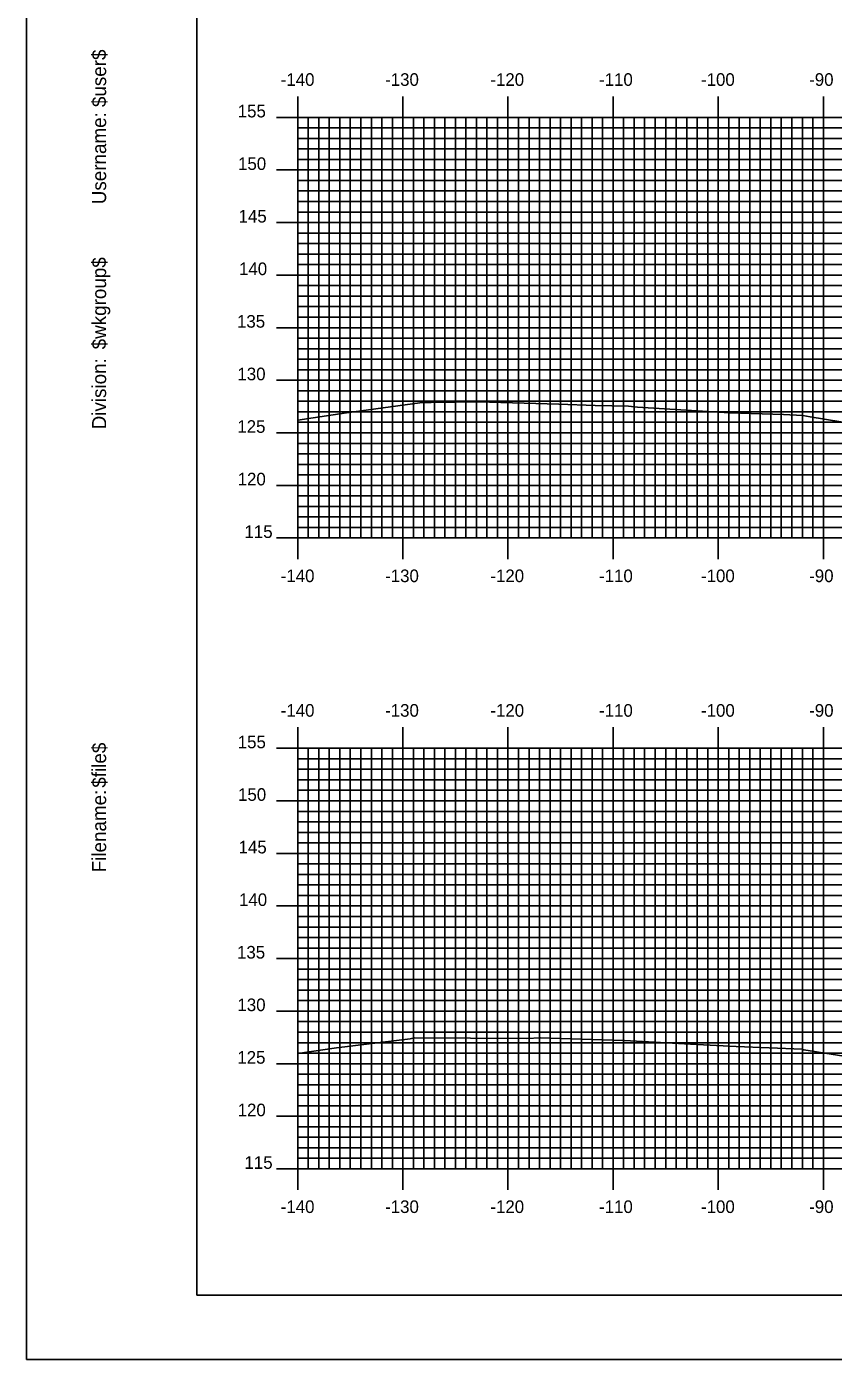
# Model space of a CAD drawing. Extents: x 854902 to 855245, y 364661 to 364881.
# Drawn here: x 854901.6 to 854978.3, y 364661.3 to 364788 of the extents above; entities that cross this region are included whole.
import ezdxf

# ---------------------------------------------------------------- set-up
doc = ezdxf.new("R2010")
doc.units = 0
for name, color, linetype in [('BORDER', 7, 'Continuous'), ('H_V ANNOTATION', 7, 'Continuous'), ('M_Roadway_Centerline', 7, 'Continuous'), ('MAJOR', 7, 'Continuous'), ('MINOR', 7, 'Continuous'), ('PLOT BOUNDARY', 7, 'Continuous'), ('S_Roadway_Centerline', 7, 'Continuous')]:
    doc.layers.add(name, color=color, linetype=linetype)

msp = doc.modelspace()

# ---------------------------------------------------------------- linework, layer by layer
at = {"layer": 'BORDER'}
msp.add_lwpolyline([(854917.75, 364667.37), (855237.75, 364667.37), (855237.75, 364877.37), (854917.75, 364877.37)], close=True, dxfattribs=at)
at = {"layer": 'MAJOR'}
for p, q in [((854927.35, 364781.37), (854927.35, 364779.37)), ((854937.35, 364781.37), (854937.35, 364779.37)), ((854947.35, 364781.37), (854947.35, 364779.37)), ((854957.35, 364781.37), (854957.35, 364779.37)), ((854967.35, 364781.37), (854967.35, 364779.37)), ((854977.35, 364781.37), (854977.35, 364779.37)), ((854925.34, 364779.37), (854927.35, 364779.37)), ((854927.35, 364779.37), (855207.35, 364779.37)), ((854927.35, 364739.37), (854927.35, 364779.37)), ((854927.35, 364739.37), (854927.35, 364779.37)), ((854927.35, 364779.37), (855207.35, 364779.37)), ((854937.35, 364739.37), (854937.35, 364779.37)), ((854947.35, 364739.37), (854947.35, 364779.37)), ((854957.35, 364739.37), (854957.35, 364779.37)), ((854967.35, 364739.37), (854967.35, 364779.37)), ((854977.35, 364739.37), (854977.35, 364779.37)), ((854925.34, 364774.37), (854927.35, 364774.37)), ((854927.35, 364774.37), (855207.35, 364774.37)), ((854925.34, 364769.37), (854927.35, 364769.37)), ((854927.35, 364769.37), (855207.35, 364769.37)), ((854925.34, 364764.37), (854927.35, 364764.37)), ((854927.35, 364764.37), (855207.35, 364764.37)), ((854925.34, 364759.37), (854927.35, 364759.37)), ((854927.35, 364759.37), (855207.35, 364759.37)), ((854925.34, 364754.37), (854927.35, 364754.37)), ((854927.35, 364754.37), (855207.35, 364754.37)), ((854925.34, 364749.37), (854927.35, 364749.37)), ((854927.35, 364749.37), (855207.35, 364749.37)), ((854925.34, 364744.37), (854927.35, 364744.37)), ((854927.35, 364744.37), (855207.35, 364744.37)), ((854925.34, 364739.37), (854927.35, 364739.37)), ((854927.35, 364739.37), (855207.35, 364739.37)), ((854927.35, 364739.37), (855207.35, 364739.37)), ((854927.35, 364737.37), (854927.35, 364739.37)), ((854937.35, 364737.37), (854937.35, 364739.37)), ((854947.35, 364737.37), (854947.35, 364739.37)), ((854957.35, 364737.37), (854957.35, 364739.37)), ((854967.35, 364737.37), (854967.35, 364739.37)), ((854977.35, 364737.37), (854977.35, 364739.37)), ((854927.35, 364721.37), (854927.35, 364719.37)), ((854937.35, 364721.37), (854937.35, 364719.37)), ((854947.35, 364721.37), (854947.35, 364719.37)), ((854957.35, 364721.37), (854957.35, 364719.37)), ((854967.35, 364721.37), (854967.35, 364719.37)), ((854977.35, 364721.37), (854977.35, 364719.37)), ((854925.34, 364719.37), (854927.35, 364719.37)), ((854927.35, 364719.37), (855207.35, 364719.37)), ((854927.35, 364679.37), (854927.35, 364719.37)), ((854927.35, 364679.37), (854927.35, 364719.37)), ((854927.35, 364719.37), (855207.35, 364719.37)), ((854937.35, 364679.37), (854937.35, 364719.37)), ((854947.35, 364679.37), (854947.35, 364719.37)), ((854957.35, 364679.37), (854957.35, 364719.37)), ((854967.35, 364679.37), (854967.35, 364719.37)), ((854977.35, 364679.37), (854977.35, 364719.37)), ((854925.34, 364714.37), (854927.35, 364714.37)), ((854927.35, 364714.37), (855207.35, 364714.37)), ((854925.34, 364709.37), (854927.35, 364709.37)), ((854927.35, 364709.37), (855207.35, 364709.37)), ((854925.34, 364704.37), (854927.35, 364704.37)), ((854927.35, 364704.37), (855207.35, 364704.37)), ((854925.34, 364699.37), (854927.35, 364699.37)), ((854927.35, 364699.37), (855207.35, 364699.37)), ((854925.34, 364694.37), (854927.35, 364694.37)), ((854927.35, 364694.37), (855207.35, 364694.37)), ((854925.34, 364689.37), (854927.35, 364689.37)), ((854927.35, 364689.37), (855207.35, 364689.37)), ((854925.34, 364684.37), (854927.35, 364684.37)), ((854927.35, 364684.37), (855207.35, 364684.37)), ((854925.34, 364679.37), (854927.35, 364679.37)), ((854927.35, 364679.37), (855207.35, 364679.37)), ((854927.35, 364679.37), (855207.35, 364679.37)), ((854927.35, 364677.37), (854927.35, 364679.37)), ((854937.35, 364677.37), (854937.35, 364679.37)), ((854947.35, 364677.37), (854947.35, 364679.37)), ((854957.35, 364677.37), (854957.35, 364679.37)), ((854967.35, 364677.37), (854967.35, 364679.37)), ((854977.35, 364677.37), (854977.35, 364679.37))]:
    msp.add_line(p, q, dxfattribs=at)
at = {"layer": 'MINOR'}
for p, q in [((854927.35, 364778.37), (855207.35, 364778.37)), ((854927.35, 364778.37), (854929.35, 364778.37)), ((854928.35, 364739.37), (854928.35, 364779.37)), ((854929.35, 364739.37), (854929.35, 364779.37)), ((854930.35, 364739.37), (854930.35, 364779.37)), ((854931.35, 364739.37), (854931.35, 364779.37)), ((854932.35, 364739.37), (854932.35, 364779.37)), ((854933.35, 364739.37), (854933.35, 364779.37)), ((854934.35, 364739.37), (854934.35, 364779.37)), ((854935.35, 364739.37), (854935.35, 364779.37)), ((854936.35, 364739.37), (854936.35, 364779.37)), ((854938.35, 364739.37), (854938.35, 364779.37)), ((854939.35, 364739.37), (854939.35, 364779.37)), ((854940.35, 364739.37), (854940.35, 364779.37)), ((854941.35, 364739.37), (854941.35, 364779.37)), ((854942.35, 364739.37), (854942.35, 364779.37)), ((854943.35, 364739.37), (854943.35, 364779.37)), ((854944.35, 364739.37), (854944.35, 364779.37)), ((854945.35, 364739.37), (854945.35, 364779.37)), ((854946.35, 364739.37), (854946.35, 364779.37)), ((854948.35, 364739.37), (854948.35, 364779.37)), ((854949.35, 364739.37), (854949.35, 364779.37)), ((854950.35, 364739.37), (854950.35, 364779.37)), ((854951.35, 364739.37), (854951.35, 364779.37)), ((854952.35, 364739.37), (854952.35, 364779.37)), ((854953.35, 364739.37), (854953.35, 364779.37)), ((854954.35, 364739.37), (854954.35, 364779.37)), ((854955.35, 364739.37), (854955.35, 364779.37)), ((854956.35, 364739.37), (854956.35, 364779.37)), ((854958.35, 364739.37), (854958.35, 364779.37)), ((854959.35, 364739.37), (854959.35, 364779.37)), ((854960.35, 364739.37), (854960.35, 364779.37)), ((854961.35, 364739.37), (854961.35, 364779.37)), ((854962.35, 364739.37), (854962.35, 364779.37)), ((854963.35, 364739.37), (854963.35, 364779.37)), ((854964.35, 364739.37), (854964.35, 364779.37)), ((854965.35, 364739.37), (854965.35, 364779.37)), ((854966.35, 364739.37), (854966.35, 364779.37)), ((854968.35, 364739.37), (854968.35, 364779.37)), ((854969.35, 364739.37), (854969.35, 364779.37)), ((854970.35, 364739.37), (854970.35, 364779.37)), ((854971.35, 364739.37), (854971.35, 364779.37)), ((854972.35, 364739.37), (854972.35, 364779.37)), ((854973.35, 364739.37), (854973.35, 364779.37)), ((854974.35, 364739.37), (854974.35, 364779.37)), ((854975.35, 364739.37), (854975.35, 364779.37)), ((854976.35, 364739.37), (854976.35, 364779.37)), ((854927.35, 364777.37), (855207.35, 364777.37)), ((854927.35, 364777.37), (854929.35, 364777.37)), ((854927.35, 364776.37), (855207.35, 364776.37)), ((854927.35, 364776.37), (854929.35, 364776.37)), ((854927.35, 364775.37), (855207.35, 364775.37)), ((854927.35, 364775.37), (854929.35, 364775.37)), ((854927.35, 364773.37), (855207.35, 364773.37)), ((854927.35, 364773.37), (854929.35, 364773.37)), ((854927.35, 364772.37), (855207.35, 364772.37)), ((854927.35, 364772.37), (854929.35, 364772.37)), ((854927.35, 364771.37), (855207.35, 364771.37)), ((854927.35, 364771.37), (854929.35, 364771.37)), ((854927.35, 364770.37), (855207.35, 364770.37)), ((854927.35, 364770.37), (854929.35, 364770.37)), ((854927.35, 364768.37), (855207.35, 364768.37)), ((854927.35, 364768.37), (854929.35, 364768.37)), ((854927.35, 364767.37), (855207.35, 364767.37)), ((854927.35, 364767.37), (854929.35, 364767.37)), ((854927.35, 364766.37), (855207.35, 364766.37)), ((854927.35, 364766.37), (854929.35, 364766.37)), ((854927.35, 364765.37), (855207.35, 364765.37)), ((854927.35, 364765.37), (854929.35, 364765.37)), ((854927.35, 364763.37), (855207.35, 364763.37)), ((854927.35, 364763.37), (854929.35, 364763.37)), ((854927.35, 364762.37), (855207.35, 364762.37)), ((854927.35, 364762.37), (854929.35, 364762.37)), ((854927.35, 364761.37), (855207.35, 364761.37)), ((854927.35, 364761.37), (854929.35, 364761.37)), ((854927.35, 364760.37), (855207.35, 364760.37)), ((854927.35, 364760.37), (854929.35, 364760.37)), ((854927.35, 364758.37), (855207.35, 364758.37)), ((854927.35, 364758.37), (854929.35, 364758.37)), ((854927.35, 364757.37), (855207.35, 364757.37)), ((854927.35, 364757.37), (854929.35, 364757.37)), ((854927.35, 364756.37), (855207.35, 364756.37)), ((854927.35, 364756.37), (854929.35, 364756.37)), ((854927.35, 364755.37), (855207.35, 364755.37)), ((854927.35, 364755.37), (854929.35, 364755.37)), ((854927.35, 364753.37), (855207.35, 364753.37)), ((854927.35, 364753.37), (854929.35, 364753.37)), ((854927.35, 364752.37), (855207.35, 364752.37)), ((854927.35, 364752.37), (854929.35, 364752.37)), ((854927.35, 364751.37), (855207.35, 364751.37)), ((854927.35, 364751.37), (854929.35, 364751.37)), ((854927.35, 364750.37), (855207.35, 364750.37)), ((854927.35, 364750.37), (854929.35, 364750.37)), ((854927.35, 364748.37), (855207.35, 364748.37)), ((854927.35, 364748.37), (854929.35, 364748.37)), ((854927.35, 364747.37), (855207.35, 364747.37)), ((854927.35, 364747.37), (854929.35, 364747.37)), ((854927.35, 364746.37), (855207.35, 364746.37)), ((854927.35, 364746.37), (854929.35, 364746.37)), ((854927.35, 364745.37), (855207.35, 364745.37)), ((854927.35, 364745.37), (854929.35, 364745.37)), ((854927.35, 364743.37), (855207.35, 364743.37)), ((854927.35, 364743.37), (854929.35, 364743.37)), ((854927.35, 364742.37), (855207.35, 364742.37)), ((854927.35, 364742.37), (854929.35, 364742.37)), ((854927.35, 364741.37), (855207.35, 364741.37)), ((854927.35, 364741.37), (854929.35, 364741.37)), ((854927.35, 364740.37), (855207.35, 364740.37)), ((854927.35, 364740.37), (854929.35, 364740.37)), ((854928.35, 364679.37), (854928.35, 364719.37)), ((854929.35, 364679.37), (854929.35, 364719.37)), ((854930.35, 364679.37), (854930.35, 364719.37)), ((854931.35, 364679.37), (854931.35, 364719.37)), ((854932.35, 364679.37), (854932.35, 364719.37)), ((854933.35, 364679.37), (854933.35, 364719.37)), ((854934.35, 364679.37), (854934.35, 364719.37)), ((854935.35, 364679.37), (854935.35, 364719.37)), ((854936.35, 364679.37), (854936.35, 364719.37)), ((854938.35, 364679.37), (854938.35, 364719.37)), ((854939.35, 364679.37), (854939.35, 364719.37)), ((854940.35, 364679.37), (854940.35, 364719.37)), ((854941.35, 364679.37), (854941.35, 364719.37)), ((854942.35, 364679.37), (854942.35, 364719.37)), ((854943.35, 364679.37), (854943.35, 364719.37)), ((854944.35, 364679.37), (854944.35, 364719.37)), ((854945.35, 364679.37), (854945.35, 364719.37)), ((854946.35, 364679.37), (854946.35, 364719.37)), ((854948.35, 364679.37), (854948.35, 364719.37)), ((854949.35, 364679.37), (854949.35, 364719.37)), ((854950.35, 364679.37), (854950.35, 364719.37)), ((854951.35, 364679.37), (854951.35, 364719.37)), ((854952.35, 364679.37), (854952.35, 364719.37)), ((854953.35, 364679.37), (854953.35, 364719.37)), ((854954.35, 364679.37), (854954.35, 364719.37)), ((854955.35, 364679.37), (854955.35, 364719.37)), ((854956.35, 364679.37), (854956.35, 364719.37)), ((854958.35, 364679.37), (854958.35, 364719.37)), ((854959.35, 364679.37), (854959.35, 364719.37)), ((854960.35, 364679.37), (854960.35, 364719.37)), ((854961.35, 364679.37), (854961.35, 364719.37)), ((854962.35, 364679.37), (854962.35, 364719.37)), ((854963.35, 364679.37), (854963.35, 364719.37)), ((854964.35, 364679.37), (854964.35, 364719.37)), ((854965.35, 364679.37), (854965.35, 364719.37)), ((854966.35, 364679.37), (854966.35, 364719.37)), ((854968.35, 364679.37), (854968.35, 364719.37)), ((854969.35, 364679.37), (854969.35, 364719.37)), ((854970.35, 364679.37), (854970.35, 364719.37)), ((854971.35, 364679.37), (854971.35, 364719.37)), ((854972.35, 364679.37), (854972.35, 364719.37)), ((854973.35, 364679.37), (854973.35, 364719.37)), ((854974.35, 364679.37), (854974.35, 364719.37)), ((854975.35, 364679.37), (854975.35, 364719.37)), ((854976.35, 364679.37), (854976.35, 364719.37)), ((854927.35, 364718.37), (855207.35, 364718.37)), ((854927.35, 364718.37), (854929.35, 364718.37)), ((854927.35, 364717.37), (855207.35, 364717.37)), ((854927.35, 364717.37), (854929.35, 364717.37)), ((854927.35, 364716.37), (855207.35, 364716.37)), ((854927.35, 364716.37), (854929.35, 364716.37)), ((854927.35, 364715.37), (855207.35, 364715.37)), ((854927.35, 364715.37), (854929.35, 364715.37)), ((854927.35, 364713.37), (855207.35, 364713.37)), ((854927.35, 364713.37), (854929.35, 364713.37)), ((854927.35, 364712.37), (855207.35, 364712.37)), ((854927.35, 364712.37), (854929.35, 364712.37)), ((854927.35, 364711.37), (855207.35, 364711.37)), ((854927.35, 364711.37), (854929.35, 364711.37)), ((854927.35, 364710.37), (855207.35, 364710.37)), ((854927.35, 364710.37), (854929.35, 364710.37)), ((854927.35, 364708.37), (855207.35, 364708.37)), ((854927.35, 364708.37), (854929.35, 364708.37)), ((854927.35, 364707.37), (855207.35, 364707.37)), ((854927.35, 364707.37), (854929.35, 364707.37)), ((854927.35, 364706.37), (855207.35, 364706.37)), ((854927.35, 364706.37), (854929.35, 364706.37)), ((854927.35, 364705.37), (855207.35, 364705.37)), ((854927.35, 364705.37), (854929.35, 364705.37)), ((854927.35, 364703.37), (855207.35, 364703.37)), ((854927.35, 364703.37), (854929.35, 364703.37)), ((854927.35, 364702.37), (855207.35, 364702.37)), ((854927.35, 364702.37), (854929.35, 364702.37)), ((854927.35, 364701.37), (855207.35, 364701.37)), ((854927.35, 364701.37), (854929.35, 364701.37)), ((854927.35, 364700.37), (855207.35, 364700.37)), ((854927.35, 364700.37), (854929.35, 364700.37)), ((854927.35, 364698.37), (855207.35, 364698.37)), ((854927.35, 364698.37), (854929.35, 364698.37)), ((854927.35, 364697.37), (855207.35, 364697.37)), ((854927.35, 364697.37), (854929.35, 364697.37)), ((854927.35, 364696.37), (855207.35, 364696.37)), ((854927.35, 364696.37), (854929.35, 364696.37)), ((854927.35, 364695.37), (855207.35, 364695.37)), ((854927.35, 364695.37), (854929.35, 364695.37)), ((854927.35, 364693.37), (855207.35, 364693.37)), ((854927.35, 364693.37), (854929.35, 364693.37)), ((854927.35, 364692.37), (855207.35, 364692.37)), ((854927.35, 364692.37), (854929.35, 364692.37)), ((854927.35, 364691.37), (855207.35, 364691.37)), ((854927.35, 364691.37), (854929.35, 364691.37)), ((854927.35, 364690.37), (855207.35, 364690.37)), ((854927.35, 364690.37), (854929.35, 364690.37)), ((854927.35, 364688.37), (855207.35, 364688.37)), ((854927.35, 364688.37), (854929.35, 364688.37)), ((854927.35, 364687.37), (855207.35, 364687.37)), ((854927.35, 364687.37), (854929.35, 364687.37)), ((854927.35, 364686.37), (855207.35, 364686.37)), ((854927.35, 364686.37), (854929.35, 364686.37)), ((854927.35, 364685.37), (855207.35, 364685.37)), ((854927.35, 364685.37), (854929.35, 364685.37)), ((854927.35, 364683.37), (855207.35, 364683.37)), ((854927.35, 364683.37), (854929.35, 364683.37)), ((854927.35, 364682.37), (855207.35, 364682.37)), ((854927.35, 364682.37), (854929.35, 364682.37)), ((854927.35, 364681.37), (855207.35, 364681.37)), ((854927.35, 364681.37), (854929.35, 364681.37)), ((854927.35, 364680.37), (855207.35, 364680.37)), ((854927.35, 364680.37), (854929.35, 364680.37))]:
    msp.add_line(p, q, dxfattribs=at)
at = {"layer": 'PLOT BOUNDARY'}
msp.add_lwpolyline([(854901.56, 364661.25), (855241.56, 364661.25), (855241.56, 364881.25), (854901.56, 364881.25)], close=True, dxfattribs=at)
at = {"layer": 'S_Roadway_Centerline'}
for points in [[(854927.35, 364750.57), (854928.81, 364750.8), (854931.98, 364751.28), (854938.95, 364752.23), (854940.03, 364752.27), (854944.47, 364752.33), (854952.18, 364752.11), (854955.63, 364751.97), (854958.82, 364751.89), (854959.68, 364751.81), (854966.88, 364751.38), (854968.46, 364751.28), (854973.55, 364751.1), (854975.41, 364751.01), (854976.1, 364750.89), (854984.86, 364749.46)], [(854927.35, 364690.34), (854931.04, 364690.88), (854938.05, 364691.75), (854938.45, 364691.83), (854949.12, 364691.76), (854950.47, 364691.82), (854953.33, 364691.72), (854958.42, 364691.58), (854964.7, 364691.24), (854969.05, 364691.01), (854975.34, 364690.76), (854975.5, 364690.69), (854988.29, 364688.65)]]:
    msp.add_lwpolyline(points, dxfattribs=at)

# ---------------------------------------------------------------- texts
at = {"layer": 'BORDER'}
for s, p in [('$user$', (854909.12, 364780.35)), ('Username:', (854909.12, 364771.11)), ('$wkgroup$', (854909.12, 364757.31)), ('Division:', (854909.12, 364749.7)), ('$file$', (854909.12, 364715.62)), ('Filename:', (854909.12, 364707.57))]:
    msp.add_text(s, height=1.339, rotation=90, dxfattribs=at).set_placement(p)
at = {"layer": 'H_V ANNOTATION'}
for s, p in [('-140', (854925.73, 364782.37)), ('-130', (854935.66, 364782.37)), ('-120', (854945.67, 364782.37)), ('-110', (854956.01, 364782.37)), ('-100', (854965.71, 364782.37)), ('-90', (854976, 364782.37)), ('155', (854921.64, 364779.37)), ('150', (854921.67, 364774.37)), ('145', (854921.72, 364769.37)), ('140', (854921.76, 364764.37)), ('135', (854921.57, 364759.37)), ('130', (854921.61, 364754.37)), ('125', (854921.6, 364749.37)), ('120', (854921.63, 364744.37)), ('115', (854922.28, 364739.37)), ('-140', (854925.73, 364735.17)), ('-130', (854935.66, 364735.17)), ('-120', (854945.67, 364735.17)), ('-110', (854956.01, 364735.17)), ('-100', (854965.71, 364735.17)), ('-90', (854976, 364735.17)), ('-140', (854925.73, 364722.37)), ('-130', (854935.66, 364722.37)), ('-120', (854945.67, 364722.37)), ('-110', (854956.01, 364722.37)), ('-100', (854965.71, 364722.37)), ('-90', (854976, 364722.37)), ('155', (854921.64, 364719.37)), ('150', (854921.67, 364714.37)), ('145', (854921.72, 364709.37)), ('140', (854921.76, 364704.37)), ('135', (854921.57, 364699.37)), ('130', (854921.61, 364694.37)), ('125', (854921.6, 364689.37)), ('120', (854921.63, 364684.37)), ('115', (854922.28, 364679.37)), ('-140', (854925.73, 364675.17)), ('-130', (854935.66, 364675.17)), ('-120', (854945.67, 364675.17)), ('-110', (854956.01, 364675.17)), ('-100', (854965.71, 364675.17)), ('-90', (854976, 364675.17))]:
    msp.add_text(s, height=1.2, dxfattribs=at).set_placement(p)
at = {"layer": 'M_Roadway_Centerline'}
for s, p in [('C', (854958.81, 364751.89)), ('L', (854958.82, 364751.89)), ('C', (854958.41, 364691.58)), ('L', (854958.42, 364691.58))]:
    msp.add_text(s, height=0.0146, dxfattribs=at).set_placement(p)
at = {"layer": 'MAJOR'}
for p in [(854927.34, 364739.37), (854927.34, 364679.37)]:
    msp.add_text('-', height=0.012, dxfattribs=at).set_placement(p)

doc.saveas('drawing.dxf')
